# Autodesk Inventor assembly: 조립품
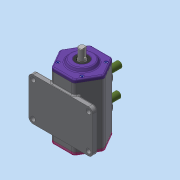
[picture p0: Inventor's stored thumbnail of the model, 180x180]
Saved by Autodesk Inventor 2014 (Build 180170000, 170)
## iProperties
Created: 2021-06
Part Number: 조립품
Document SubType Name: Assembly
Designer: net
Author: net
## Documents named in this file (11)
- C:\Users\net\Desktop\710606V1039\조립품.iam
- C:\Users\net\Desktop\710606V1039\본체.ipt
- C:\Users\net\Desktop\710606V1039\편심축.ipt
- C:\Users\net\Desktop\710606V1039\뒷커버.ipt
- C:\Users\net\Desktop\710606V1039\앞커버.ipt
- C:\Users\net\Desktop\710606V1039\부시.ipt
- C:\Users\net\Desktop\710606V1039\슬라이더.ipt
- C:\Users\net\Desktop\710606V1039\볼트 M4.ipt
- C:\Users\net\Desktop\710606V1039\베어링 6203.ipt
- C:\Users\net\Desktop\710606V1039\베어링 6302.ipt
- C:\Users\net\Desktop\710606V1039\오일실.ipt
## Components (10 placed, 3 different names)
1. 7-베어링 6203:1
2. 8-오일실:1
3. 9-M4-소켓머리:2
4. 9-M4-소켓머리:3
5. 9-M4-소켓머리:4
6. 9-M4-소켓머리:5
7. 9-M4-소켓머리:1
8. 9-M4-소켓머리:6
9. 9-M4-소켓머리:7
10. 9-M4-소켓머리:8
